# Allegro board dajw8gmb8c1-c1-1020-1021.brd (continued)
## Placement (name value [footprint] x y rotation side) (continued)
PC177  0.1U/25V_4  [CC0402]  171.77 26.01 90 bottom
PC178  2200P/50V_4  [CC0402]  154.32 25.67 180 bottom
PC179  *2200P/50V_4_NC  [CC0402]  119.91 25.04 180 bottom
PC180  0.1U/25V_4  [CC0402]  154.32 24.53 180 bottom
PC181  *2200P/50V_4_NC  [CC0402]  136.92 24.4 0 bottom
PC182  *2200P/50V_4_NC  [CC0402]  166.38 22.63 270 bottom
PC183  4.7U/25V_8  [CC0805]  152.38 20.69 270 bottom
PC184  4.7U/25V_8  [CC0805]  125.1 21.7 270 bottom
PC185  4.7U/25V_8  [CC0805]  123.07 21.7 270 bottom
PC186  0.1U/25V_4  [CC0402]  150.73 20.43 90 bottom
PC187  0.1U/25V_4  [CC0402]  129.32 21.32 270 bottom
PC188  0.1U/25V_4  [CC0402]  127.11 21.32 270 bottom
PC189  4.7U/25V_8  [CC0805]  134.87 19.74 270 bottom
PC190  4.7U/25V_8  [CC0805]  132.73 19.73 270 bottom
PC191  10U/25V_8  [CC0805]  32.23 17.48 0 bottom
PC192  4.7U/25V_8  [CC0805]  156.22 17.29 180 bottom
PC193  2200P/50V_4  [CC0402]  134.28 16.78 90 bottom
PC194  0.1U/25V_4  [CC0402]  135.35 16.77 90 bottom
PC195  2200P/50V_4  [CC0402]  124.16 16.95 90 bottom
PC196  0.1U/25V_4  [CC0402]  122.89 16.95 270 bottom
PC197  10U/25V_8  [CC0805]  32.24 15.44 0 bottom
PC198  0.1U/25V_4  [CC0402]  32.49 13.83 0 bottom
PC199  0.01U/25V_4  [CC0402]  30.84 13.32 90 bottom
PC200  0.1U/25V_4  [CC0402]  32.49 12.69 0 bottom
PC240  4.7U/6.3V_6  [CC0603]  63.2 19.57 90 top
PC241  0.022U/16V_4  [CC0402]  53.32 20.35 90 top
PC249  1U/6.3V/X5R  [CC0402]  243.19 43.17 270 top
PC250  0.1U/16V/X7R_4  [CC0402]  249.28 44.31 270 top
PC251  10U/6.3V/X5R_6  [CC0603]  250.43 44.56 270 top
PC252  0.1U/16V/X7R_4  [CC0402]  251.7 40.5 90 top
PC253  10U/6.3V/X5R_6  [CC0603]  250.93 42.66 180 top
PC254  1000P/50V_4  [CC0402]  233.24 48.2 270 top
PD1  *Dis@BAT54C T/R_NC  [UMT_213-3-1_3]  249.03 48.12 90 top
PD2  SDM10K45-7-F  [DSMV]  42.53 29.83 180 top
PD3  SDM10K45-7-F  [DSM]  178.07 29.61 180 top
PD4  *Dis@1N4448WS_NC  [DSM]  89.01 23.99 270 top
PD5  1SS355  [DSMV]  43.01 19.7 0 top
PD6  *1N4448WS_NC  [DSM]  212.5 118.31 0 bottom
PD7  *Dis@1N4448WS_NC  [DSM]  262.11 47.99 180 top
PD8  1SS355  [DSMV]  61.77 25.51 180 top
PL1  1UH (PCMC063T-1R0MN)  [CHOKE-MPL73-1R5]  189.14 122.95 180 bottom
PL2  2.2UH (TMPC0402HP-2R2MG-Z01)  [L4_06X4_06-1_8]  161.45 121.18 0 bottom
PL3  0.24UH (ETQP4LR24AFM)  [CHOKE-PCMC063T-R82MN-4P-SMT]  139.4 120.84 180 bottom
PL4  *0.24UH (ETQP4LR24AFM)_NC  [CHOKE-PCMC063T-R82MN-4P-SMT]  129.93 120.84 0 bottom
PL5  0.36UH/30A  [CHOKE-ETQP4L]  220.07 64.25 180 bottom
PL6  0.36UH/30A  [CHOKE-ETQP4L]  207.43 63.25 90 bottom
PL7  4.7UH (PCMC063T-4R7MN)  [CHOKE-MPLC0730L3R3]  38.03 24.85 270 bottom
PL8  0.82UH_(EM-82BM05V04)  [CHOKE-MPL73-1R5]  159.14 26.39 90 bottom
PL9  2.2UH_(EM-22AM05V04)  [CHOKE-MPL73-1R5]  113.04 19.96 180 bottom
PL10  2.2UH_(EM-22AM05V04)  [CHOKE-MPL73-1R5]  144.99 19.5 180 bottom
PQ1  FDMC7678  [POWER-FDMC7678-5P]  171.18 119.37 180 top
PQ2  *Dis@2N7002KW_SC70_NC  [UMT_213-3-1_3]  215.25 118.35 0 top
PQ3  Dis@QM3002V  [TSOP6-2_8-95]  221.47 117.72 90 top
PQ4  FDMC7678  [POWER-FDMC7678-5P]  175.98 117 270 top
PQ5  *DMN66D0LDW-7_NC  [SOT-363]  20.81 89.47 180 top
PQ6  *DMN66D0LDW-7_NC  [SOT-363]  20.73 84.46 90 top
PQ7  Dis@FDMC7678  [POWER-FDMC7678-5P]  226.8 71.61 90 top
PQ8  *Dis@2N7002KW_SC70_NC  [UMT_213-3-1_3]  245.35 49.26 270 top
PQ9  FDC8886  [SSOT6-2_8-95]  190.61 39.61 0 top
PQ10  FDC8886  [SSOT6-2_8-95]  190.61 35.29 180 top
PQ12  METR5213-G  [UMT_213-3-1_3]  123.46 31.9 270 top
PQ13  2N7002KW_SC70  [UMT_213-3-1_3]  126.25 31.77 90 top
PQ14  2N7002KW_SC70  [UMT_213-3-1_3]  140.85 31.77 0 top
PQ15  METR5213-G  [UMT_213-3-1_3]  144.66 31.77 0 top
PQ16  DMN66D0LDW-7  [SOT-363]  50.48 23.53 270 top
PQ17  MMDT2907A  [SOT363-2_1-65-6P]  35.72 25.49 270 top
PQ18  Dis@METR5213-G  [UMT_213-3-1_3]  91.55 23.74 270 top
PQ19  FDC8886  [SSOT6-2_8-95]  235.95 22.85 270 top
PQ20  FDMC4435BZ  [PG-TSDSON-8-8P-R]  38.55 20.55 90 top
PQ21  2N7002W  [UMT_213-3-1_3]  55.84 20.08 180 top
PQ22  2N7002W  [UMT_213-3-1_3]  32.72 14.13 270 top
PQ23  FDMC8884  [PG-TSDSON-8-8P-R]  195.77 124.78 180 bottom
PQ24  *CSD97374CQ4M_NC  [SON8-4_5X3_5-5-9P-SMT]  122.66 122.59 270 bottom
PQ25  Dis@2N7002KW_SC70  [UMT_213-3-1_3]  214.99 121.14 180 bottom
PQ26  CSD97374CQ4M  [SON8-4_5X3_5-5-9P-SMT]  146.87 119.52 90 bottom
PQ27  Dis@2N7002KW_SC70  [UMT_213-3-1_3]  217.41 118.35 180 bottom
PQ28  FDMS0310AS  [SO-8FL-5P]  196.2 118.22 0 bottom
PQ29  Dis@2N7002KW_SC70  [UMT_213-3-1_3]  222.99 116.7 0 bottom
PQ30  Dis@MDU1512RH  [SO-8FL-5P]  195.69 111.62 0 bottom
PQ31  *IMD2AT108_NC  [SC74-2_8-95-6P]  23.77 90.9 270 bottom
PQ32  AON7403  [PG-TSDSON-8-8P-R]  19.29 87.49 90 bottom
PQ33  *Dis@2N7002KW_SC70_NC  [UMT_213-3-1_3]  228.07 71.61 180 bottom
PQ34  *Dis@2N7002KW_SC70_NC  [UMT_213-3-1_3]  188.07 67.8 0 bottom
PQ35  FDMC4435BZ  [PG-TSDSON-8-8P-R]  30.97 60.31 270 bottom
PQ36  FDMS0308S  [SO-8FL-5P]  225.1 56.29 270 bottom
PQ37  *Dis@2N7002KW_SC70_NC  [UMT_213-3-1_3]  196.71 55.87 0 bottom
PQ38  FDMS7682  [SO-8FL-5P]  217.04 54.88 0 bottom
PQ39  FDMS0308S  [SO-8FL-5P]  204.43 54.3 270 bottom
PQ40  FDMS7682  [SO-8FL-5P]  210.98 52.35 90 bottom
PQ41  Dis@METR5213-G  [UMT_213-3-1_3]  255.76 48.37 0 top
PQ42  FDMC8884  [PG-TSDSON-8-8P-R]  35.67 31.86 90 bottom
PQ43  FDMC8884  [PG-TSDSON-8-8P-R]  39.61 31.86 270 bottom
PQ44  FDMC7692S  [PG-TSDSON-8-8P-R]  119.65 22.37 0 bottom
PQ45  FDMC7692S  [PG-TSDSON-8-8P-R]  138.36 21.86 180 bottom
PQ46  FDMC8884  [PG-TSDSON-8-8P-R]  155.87 20.34 0 bottom
PQ47  FDMS0310AS  [SO-8FL-5P]  161.05 19.2 0 bottom
PQ48  FDMC8884  [PG-TSDSON-8-8P-R]  119.62 18.3 180 bottom
PQ49  FDMC8884  [PG-TSDSON-8-8P-R]  138.31 17.67 0 bottom
PQ50  DMN66D0LDW-7  [SOT-363]  60.56 19.8 180 top
PQ901  BC856B  [SOT23_123-2_37-1_9-1_11H]  59.55 22.72 90 top
PR1  10_6  [RC0603]  207.3 122.97 270 top
PR2  *0_4/S  [SHORT0402]  116.19 121.27 180 top
PR3  *0_4_NC  [RC0402]  116.19 120.13 0 top
PR4  2.2K/F_4  [RC0402]  108.82 119.87 270 top
PR6  130_4  [RC0402]  115.17 118.99 0 top
PR7  *0_4/S  [SHORT0402]  208.39 118.96 0 top
PR8  *0_2/S  [SHORT0201]  184.41 118.88 0 top
PR9  Dis@22_8  [RC0805]  211.56 118.35 180 top
PR10  54.9/F_4  [RC0402]  115.17 117.97 0 top
PR11  1K_4  [RC0402]  115.93 116.83 180 top
PR12  100_4  [RC0402]  164.83 116.45 270 top
PR13  *0_4/S  [SHORT0402]  107.3 117.97 180 top
PR14  *0_4_SHORT_NC  [SHORT0402]  169.65 114.92 90 top
PR15  10K_4  [RC0402]  180.5 117.21 270 top
PR16  150K/F_4  [RC0402]  106.66 111.75 90 top
PR17  75K/F_4  [RC0402]  107.68 111.75 90 top
PR18  150K/F_4  [RC0402]  109.08 111.75 90 top
PR19  *562K/F_4_NC  [RC0402]  106.28 109.33 270 top
PR20  499K/F_4  [RC0402]  107.42 109.33 270 top
PR21  9.31K/F_4  [RC0402]  108.57 109.33 270 top
PR22  *2.4K_12_NC  [RC1206]  20.15 91.66 180 top
PR23  *1K_4_NC  [RC0402]  18.28 89.08 270 top
PR24  *10K_4_NC  [RC0402]  16.76 88.69 180 top
PR25  *0_4_NC  [RC0402]  22.29 85.5 90 top
PR26  *6.8K/F_4_NC  [RC0402]  22.29 83.35 270 top
PR27  *6.8K/F_4_NC  [RC0402]  23.43 83.34 270 top
PR28  *1K_4_NC  [RC0402]  21.13 81.29 0 top
PR29  *Dis@22_8_NC  [RC0805]  188.07 66.92 0 top
PR31  100R/J_4  [RC0402]  194.64 61.74 90 top
PR32  *0_4_NC  [RC0402]  112.76 60.82 90 top
PR33  100R/J_4  [RC0402]  195.67 60.2 180 top
PR34  2_6  [RC0603]  234.41 57.37 270 top
PR35  2.2R_8  [RC0805]  231 57.26 180 top
PR36  10K/F_4  [RC0402]  233.3 57.15 90 top
PR37  5.9K/F_4  [RC0402]  238.1 57.07 90 top
PR38  *short  [SHORT-1A]  240.14 56.76 180 top
PR39  *0_4/S  [SHORT0402]  111.36 56.25 90 top
PR40  82K/F_4  [RC0402]  239.77 55.24 0 top
PR41  *0_4_NC  [RC0402]  111.36 54.09 270 top
PR42  43K/F_4  [RC0402]  238.73 53.19 180 top
PR43  51_4  [RC0402]  241.01 53.19 180 top
PR44  10K/F_4  [RC0402]  240.99 52.18 180 top
PR45  21K/F_4  [RC0402]  228.35 51.76 0 top
PR46  18K/F_4  [RC0402]  239.26 50.65 270 top
PR47  20K/F_4  [RC0402]  241.3 50.64 90 top
PR48  2K/F_4  [RC0402]  240.29 50.63 90 top
PR49  Dis@0_4  [RC0402]  248.39 50.53 0 top
PR50  *Dis@0_4_SHORT_NC  [SHORT0402]  243.19 49.9 270 top
PR51  *0_4/S  [SHORT0402]  238.74 49.11 180 top
PR52  *0_4_NC  [RC0402]  234.77 48.63 0 top
PR53  2.2R_8  [RC0805]  230.86 48.12 180 top
PR54  DIS@100K_4  [RC0402]  232.73 46.48 180 top
PR55  *0_4/S  [SHORT0402]  236.35 48.12 270 top
PR56  20K/F_4  [RC0402]  237.94 48.1 0 top
PR57  *Dis@100K_4_NC  [RC0402]  242.96 46.8 270 top
PR58  10K/F_4  [RC0402]  234.77 47.61 180 top
PR59  *Dis@100K_4_NC  [RC0402]  245.47 46.72 180 top
PR60  *0_4/S  [SHORT0402]  234.78 46.59 180 top
PR61  *0_4_SHORT_NC  [SHORT0402]  279.26 39.48 0 top
PR62  10_6  [RC0603]  49.18 32.75 270 top
PR63  7.5_6  [RC0603]  50.4 32.75 90 top
PR64  22K/F_4  [RC0402]  51.8 30.47 0 top
PR65  100K/F_4  [RC0402]  52.18 32.63 0 top
PR66  *0_4/S  [SHORT0402]  169.65 33.77 0 top
PR67  316K/F_4  [RC0402]  53.42 30.02 90 top
PR68  2.2_8  [RC0805]  35.38 33.48 270 top
PR69  6.65K/F_4  [RC0402]  130.43 33.42 0 top
PR70  *SJ0402_NC  [SHORT0402]  51.57 29.35 0 top
PR71  1K_4  [RC0402]  191.63 32.88 180 top
PR72  0_6  [RC0603]  43.39 28.31 0 top
PR73  *0_6_SHORT_NC  [SHORT0603]  276.54 35.47 90 top
PR74  10K/F_4  [RC0402]  134.25 32.53 270 top
PR75  15.4K/F_4  [RC0402]  135.39 32.53 270 top
PR76  10K/F_4  [RC0402]  130.43 32.41 0 top
PR77  12K/F_4  [RC0402]  174.99 32.37 0 top
PR78  100K/F_4  [RC0402]  120.28 32.15 180 top
PR79  90.9K/F_4  [RC0402]  128.1 32.14 270 top
PR80  619K/F_4  [RC0402]  169.94 31.9 90 top
PR81  15K/F_4  [RC0402]  173.37 31.9 270 top
PR82  *0_4_NC  [RC0402]  171.05 31.86 270 top
PR83  *SJ0402_NC  [SHORT0402]  51.57 28.21 0 top
PR85  90.9K/F_4  [RC0402]  136.78 31.01 180 top
PR86  100K/F_4  [RC0402]  177.18 31.03 180 top
PR87  35.7K/F_4  [RC0402]  53.09 26.81 270 top
PR88  10_6  [RC0603]  168.16 30.21 180 top
PR89  *10K/F_4_NC  [RC0402]  136.78 29.87 0 top
PR90  *0_4/S  [SHORT0402]  141.49 29.1 90 top
PR91  100K/F_4  [RC0402]  142.63 29.1 90 top
PR92  2_6  [RC0603]  137.07 28.6 0 top
PR93  220K_4  [RC0402]  36.5 28.55 180 top
PR94  220K/F_4  [RC0402]  53.1 24.66 270 top
PR95  1M_4  [RC0402]  34.98 28.03 270 top
PR96  10K_4  [RC0402]  48.91 24.41 270 top
PR97  220K_4  [RC0402]  36.5 27.53 0 top
PR98  2_6  [RC0603]  124.75 27.33 0 top
PR99  7.5K/F_4  [RC0402]  168.41 26.94 180 top
PR100  Dis@1M_4  [RC0402]  93.45 24.75 90 top
PR101  Dis@1M_4  [RC0402]  94.47 24.75 270 top
PR102  12.4K/F_4  [RC0402]  52.04 22.86 270 top
PR103  10_12  [RC1206]  43.49 23.66 270 top
PR104  10K/F_4  [RC0402]  48.91 22.38 90 top
PR105  *Dis@0_4/S  [SHORT0402]  87.36 25.13 270 top
PR106  *665K/F_4_NC  [RC0402]  128.66 23.91 270 top
PR107  *330K/F_4_NC  [RC0402]  129.81 23.89 90 top
PR108  267K/F_4  [RC0402]  47.48 21.83 180 bottom
PR109  1M_4  [RC0402]  36.17 22.92 270 top
PR110  2M/F_4  [RC0402]  49.06 20.31 90 bottom
PR111  120K/F_4  [RC0402]  47.48 20.81 0 bottom
PR112  12.4K/F_4  [RC0402]  47.48 18.78 0 bottom
PR113  10_8  [RC0805]  131.46 21.61 90 top
PR114  1K_6  [RC0603]  35.06 21.48 90 top
PR115  10K/F_4  [RC0402]  47.48 19.8 180 bottom
PR116  1K_4  [RC0402]  233.79 19.47 270 top
PR117  22_6  [RC0603]  198.99 19.29 0 top
PR118  470_8  [RC0805]  32.42 17.08 0 top
PR119  2.87K/F_4  [RC0402]  135.7 126.1 0 bottom
PR120  2.2_8  [RC0805]  147.3 125.59 180 bottom
PR121  *2.87K/F_4_NC  [RC0402]  129.65 125.49 90 bottom
PR122  *1.74K/F_4_NC  [RC0402]  128.51 125.49 270 bottom
PR123  1.6K/F_4  [RC0402]  137.93 125.41 270 bottom
PR124  *0_4_NC  [RC0402]  209.02 125.08 270 bottom
PR125  *10K/NTC/TSM0B103J4252RE_4_NC  [RC0402]  132.16 125 0 bottom
PR126  10K/NTC/TSM0B103J4252RE_4  [RC0402]  135.87 125.08 0 bottom
PR127  76.8K/F_4  [RC0402]  169.2 124.8 90 bottom
PR128  2_6  [RC0603]  205.87 124.64 180 bottom
PR129  1K_4  [RC0402]  163.33 124.4 0 bottom
PR130  *0_4/S  [SHORT0402]  210.93 124.07 0 bottom
PR131  *0_6_NC  [RC0603]  118.6 123.38 0 bottom
PR132  10_6  [RC0603]  115.86 123.35 180 bottom
PR133  51.1K/F_4  [RC0402]  169.99 123.15 180 bottom
PR134  *0_4_NC  [RC0402]  211.93 122.88 0 bottom
PR135  *2.2_6_NC  [RC0603]  194.88 122.08 0 bottom
PR136  10K/F_4  [RC0402]  211.93 121.86 0 bottom
PR137  *0_4/S  [SHORT0402]  117.33 121.65 90 bottom
PR138  *0_4/S  [SHORT0402]  116.19 121.65 90 bottom
PR139  5.76K/F_4  [RC0402]  106.97 120.81 0 bottom
PR140  100K/F_4  [RC0402]  210.91 120.72 0 bottom
PR141  Dis@1M_4  [RC0402]  218.17 120.64 0 bottom
PR142  *0_4/S  [SHORT0402]  115.04 120.64 90 bottom
PR143  10K/F_4  [RC0402]  109.13 120.61 0 bottom
PR145  *0_4/S  [SHORT0402]  112.94 120.33 90 bottom
PR146  DIS@120K/F_4  [RC0402]  221.09 119.87 180 bottom
PR147  *0_4_NC  [RC0402]  210.91 119.7 0 bottom
PR148  *0_4_NC  [RC0402]  208.18 118.79 90 bottom
PR149  61.9K/F_4  [RC0402]  209.21 118.78 270 bottom
PR150  10K/F_4  [RC0402]  207.05 118.78 270 bottom
PR151  Dis@1M_4  [RC0402]  221.09 118.73 0 bottom
PR152  *0_4/S  [SHORT0402]  107.04 118.76 0 bottom
PR153  10_6  [RC0603]  115.83 118.3 180 bottom
PR154  *0_4/S  [SHORT0402]  105.34 118.3 270 bottom
PR155  0_6  [RC0603]  150.81 118.02 180 bottom
PR156  *0_4/S  [SHORT0402]  107.04 117.74 0 bottom
PR158  *2.2_8_NC  [RC0805]  124.03 116.67 0 bottom
PR159  *0_4_NC  [RC0402]  115.46 116.19 180 bottom
PR160  *16K/F_4_NC  [RC0402]  105.32 116.14 90 bottom
PR161  *0_4_NC  [RC0402]  115.48 115.05 180 bottom
PR162  *0_4_NC  [RC0402]  118.09 114.16 180 bottom
PR163  *0_4/S  [SHORT0402]  115.48 114.03 0 bottom
PR164  63.4K/F_4  [RC0402]  105.37 113.91 270 bottom
PR165  *0_4/S  [SHORT0402]  118.09 113.02 0 bottom
PR166  348K/F_4  [RC0402]  110.98 111.75 90 bottom
PR167  *10K/F_4_NC  [RC0402]  106.61 111.72 90 bottom
PR168  10K/F_4  [RC0402]  105.47 111.72 270 bottom
PR169  39K/F_4  [RC0402]  107.7 111.71 90 bottom
PR170  75K/F_4  [RC0402]  110.35 110.1 0 bottom
PR171  10K/F_4  [RC0402]  108.24 110.07 180 bottom
PR172  100K/NTC/B4250_4  [RC0402]  106.08 110.07 180 bottom
PR173  240K_4  [RC0402]  21.77 91.35 90 bottom
PR174  47K_4  [RC0402]  21.77 89.26 90 bottom
PR175  Dis@22_8  [RC0805]  231.05 72.5 90 bottom
PR177  NTC_100K_4  [RC0402]  213.11 59.27 270 bottom
PR178  *0_4/S  [SHORT0402]  233.41 58.79 0 bottom
PR179  Dis@22_8  [RC0805]  194.29 58.66 180 bottom
PR180  10K_4  [RC0402]  30.18 57.34 180 bottom
PR181  *10K/F_4_NC  [RC0402]  233.41 57.09 180 bottom
PR182  100K_4  [RC0402]  30.83 56.3 180 bottom
PR183  0.01_0612  [RC3216-4P]  35.18 56.04 180 bottom
PR184  2.2_6  [RC0603]  228.99 53.18 270 bottom
PR186  2.2_6  [RC0603]  200.54 52.56 270 bottom
PR188  Dis@1M_4  [RC0402]  253.5 47.74 270 top
PR189  *0_4/S  [SHORT0402]  237.62 47.23 0 bottom
PR190  Dis@47K/F_4  [RC0402]  258.17 48.12 90 top
PR191  Dis@1M_4  [RC0402]  253.5 49.77 270 top
PR192  *0_4/S  [SHORT0402]  237.62 46.22 0 bottom
PR193  *SJ0402_NC  [SHORT0402]  45.45 20.81 0 bottom
PR194  *0_2/S  [SHORT0201]  115.95 29.37 0 bottom
PR195  *0_2/S  [SHORT0201]  166.63 29.12 90 bottom
PR196  *0_2/S  [SHORT0201]  145.55 26.82 180 bottom
PR197  2_6  [RC0603]  173.01 26.28 90 bottom
PR198  *2.2_6_NC  [RC0603]  117.49 25.04 0 bottom
PR199  *2.2_6_NC  [RC0603]  139.33 24.4 180 bottom
PR200  *2.2_6_NC  [RC0603]  164.22 23.06 0 bottom
PR201  0.01_0612  [RC3216-4P]  35.82 18.43 180 bottom
PR202  330_4  [RC0402]  25.51 13.07 270 bottom
PR203  330_4  [RC0402]  27.35 11.73 180 bottom
PR204  200K/J_4  [RC0402]  29.52 11.72 0 bottom
PR205  1K/F_4  [RC0402]  31.73 11.67 180 bottom
PR206  *0_4_NC  [RC0402]  106.36 116.32 90 top
PR207  1K_4  [RC0402]  194.7 40.17 90 top
PR424  100K_4  [RC0402]  57.13 24.12 90 top
PR425  680K/F_4  [RC0402]  58.15 19.8 90 top
PR426  10K/F_4  [RC0402]  63.2 22.08 90 top
PR427  100K_4  [RC0402]  63.59 17.77 180 top
PR428  150K_4  [RC0402]  52.31 20.35 270 top
PR432  3.83K/F  [RC0402]  250.68 40.5 90 top
PR434  10K/F_4  [RC0402]  249.66 40.5 90 top
PU1  NCP81172MNTXG  [QFN24-4X4-5-25P]  234.15 52.64 0 top
PU2  TPS22965DSGR  [SON8-2X2-5-9P]  282.18 39.74 270 top
PU3  BQ24737RGRR  [PVQFN20-3_5X3_5-5-25P]  47.73 28.29 0 top
PU4  RT8223PZQW  [QFN24-4X4-5-25P]  131.46 28.09 180 top
PU5  RT8207LGQW  [QFN24-4X4-5-25P]  172.83 27.66 90 top
PU6  SLG55448VTR  [TQFN20-3X3-4-21P]  202.93 21.83 90 top
PU7  RT8068AZQW  [DFN10-3X3-5-11P-RT9296]  166.59 122.26 90 bottom
PU8  RT8240BZQW  [WQFN12-2X2-4-13P-SMT]  207.75 121.96 0 bottom
PU9  TPS51622RSM  [QFN32-4X4-4-42P-1H]  111.1 116.16 180 bottom
PU11  G9183-12TP1U  [SOT23-6-4_2-95-6P]  246.24 42.79 180 top
Q1  2N7002W  [UMT_213-3-1_3]  158.61 125.21 0 top
Q3  DMN66D0LDW-7  [SOT-363]  166.61 116.57 270 top
Q4  AP2319GN-HF  [SOT23_213-3_3-2]  155.68 114.54 270 top
Q5  PMF780SN  [UMT_213-3-1_3]  160.51 114.41 270 top
Q6  2N7002W  [UMT_213-3-1_3]  122.66 113.91 180 top
Q7  MMST3904-7-F  [UMT_213-3-1_3]  139.81 91.57 0 top
Q8  Dis@DTC144EUA  [UMT_213-3-1_3]  180.45 76.19 90 top
Q9  Dis@DTC144EUA  [UMT_213-3-1_3]  180.45 72.5 90 top
Q13  2N7002W  [UMT_213-3-1_3]  117.92 69.46 0 top
Q14  Dis@DMN66D0LDW-7  [SOT-363]  186.42 69.2 180 top
Q15  Dis@DMN66D0LDW-7  [SOT-363]  176 64.12 90 top
Q16  Dis@2N7002W  [UMT_213-3-1_3]  188.2 63.49 270 top
Q17  DMN66D0LDW-7  [SOT-363]  117.97 63.23 180 top
Q18  PMF780SN  [UMT_213-3-1_3]  110.22 47.36 270 top
Q19  *DMN66D0LDW-7_NC  [SOT-363]  107.3 45.71 270 top
Q20  *DMN66D0LDW-7_NC  [SOT-363]  259.57 44.56 0 top
Q21  2N7002W  [UMT_213-3-1_3]  67.9 37.12 90 top
Q23  2N7002W  [UMT_213-3-1_3]  68.44 32.75 0 top
Q24  DMN66D0LDW-7  [SOT-363]  285.3 32.75 180 top
Q25  ME2306  [SOT23_213-3_3-2]  290.05 31.48 0 top
Q26  2N7002W  [UMT_213-3-1_3]  279.64 27.67 180 top
Q27  *2N7002W_NC  [UMT_213-3-1_3]  92.06 27.16 0 top
Q28  AO3409  [SOT23_213-3_3-2]  283.07 29.45 270 bottom
Q29  *FDC8886_NC  [SSOT6-2_8-95]  83.8 28.94 0 top
Q30  *2N7002W_NC  [UMT_213-3-1_3]  57.39 27.42 90 top
Q31  ME2306  [SOT23_213-3_3-2]  287.18 25.26 270 top
Q32  DMN66D0LDW-7  [SOT-363]  187.31 19.8 270 top
Q33  2N7002W  [UMT_213-3-1_3]  189.97 19.8 270 top
Q34  DMN66D0LDW-7  [SOT-363]  174.35 86.22 270 bottom
Q35  Dis@MMST3904-7-F  [UMT_213-3-1_3]  181.72 77.28 0 bottom
Q36  Dis@DTC144EUA  [UMT_213-3-1_3]  178.29 76.69 270 bottom
Q37  DMN66D0LDW-7  [SOT-363]  171.18 74.03 270 bottom
Q38  Dis@MMST3904-7-F  [UMT_213-3-1_3]  181.72 73.77 0 bottom
Q39  *Dis@2N7002W_NC  [UMT_213-3-1_3]  187.05 72.88 90 bottom
Q40  *DMN66D0LDW-7_NC  [SOT-363]  304.78 72.38 90 bottom
Q41  2N7002W  [UMT_213-3-1_3]  269.17 45.58 0 bottom
Q42  2N7002W  [UMT_213-3-1_3]  284.21 39.99 0 bottom
Q43  2N7002W  [UMT_213-3-1_3]  240.39 35.04 180 bottom
Q44  DMN66D0LDW-7  [SC70-2_1-65-6P]  104.2 45.73 270 top
Q45  2N7002KDW  [SOT-363]  92.57 31.36 270 top
Q46  2N7002KDW  [SOT-363]  90.15 31.36 270 top
Q47  2N7002W  [UMT_213-3-1_3]  169.91 70.47 0 top
Q48  BSS138W  [UMT_213-3-1_3]  313.28 28.4 90 bottom
R1  150_6  [RC0603]  155.3 125.03 180 top
R2  150_6  [RC0603]  170.42 125.97 180 top
R3  150_6  [RC0603]  180.02 126.05 180 top
R4  330_4  [RC0402]  158.99 117.46 90 top
R5  330_4  [RC0402]  161.27 117.46 270 top
R6  *10K_4_NC  [RC0402]  170.8 114.92 270 top
R7  100K_4  [RC0402]  171.94 114.92 90 top
R8  *Dis@10K/F_4_NC  [RC0402]  173.08 114.92 90 top
R9  *10K_4_NC  [RC0402]  118.85 114.16 90 top
R10  51_4  [RC0402]  120.12 114.16 270 top
R11  10K_4  [RC0402]  158.12 113.6 90 top
R12  1K_4  [RC0402]  122.03 110.98 270 top
R13  10K_4  [RC0402]  123.05 111.24 90 top
R14  10K_4  [RC0402]  124.19 111.24 90 top
R15  *10K_4_NC  [RC0402]  125.46 111.24 90 top
R16  1K_4  [RC0402]  157.97 110.73 180 top
R17  100K_4  [RC0402]  157.97 109.71 180 top
R18  10K_4  [RC0402]  125.46 108.32 90 top
R19  *0_4_SHORT_NC  [SHORT0402]  144.25 108.19 270 top
R20  3K/F_4  [RC0402]  145.4 108.19 90 top
R21  3K/F_4  [RC0402]  146.54 108.19 270 top
R22  24.9/F_4  [RC0402]  148.19 107.68 0 top
R23  Dis@162/F_4  [RC0402]  224.77 105.52 270 top
R24  *1K_4_NC  [RC0402]  172.58 104 0 top
R25  *1K_4_NC  [RC0402]  174.73 104 180 top
R26  *short0603_NC  [SHORT0603]  20.05 103.49 180 top
R27  Dis@10K/F_4  [RC0402]  224.77 103.49 90 top
R28  *10K_4_NC  [RC0402]  174.73 102.86 180 top
R29  *short0603_NC  [SHORT0603]  20.05 102.35 180 top
R30  Dis@100/F_4  [RC0402]  179.94 101.59 90 top
R31  Dis@243/F_4  [RC0402]  224.77 101.33 270 top
R32  10K_4  [RC0402]  174.48 101.21 180 top
R33  51_4  [RC0402]  113.27 100.7 315 top
R34  *10K_4_NC  [RC0402]  174.48 100.19 180 top
R35  Dis@10K/F_4  [RC0402]  180.45 99.94 0 top
R36  10K_4  [RC0402]  172.32 98.92 180 top
R37  150_6  [RC0603]  114.79 98.67 315 top
R38  10K_4  [RC0402]  174.48 98.54 180 top
R39  10K_4  [RC0402]  172.32 97.9 180 top
R40  10K_4  [RC0402]  166.23 97.52 180 top
R41  Dis@1.33K/F_4  [RC0402]  224.77 97.14 270 top
R42  10K_4  [RC0402]  172.32 96.89 180 top
R43  8.2K/J_4  [RC0402]  166.23 96.38 180 top
R44  *120/F_4_NC  [RC0402]  312.53 96 90 top
R45  10K_4  [RC0402]  172.32 95.87 180 top
R46  10K_4  [RC0402]  166.23 95.36 180 top
R47  Dis@1.33K/F_4  [RC0402]  224.77 95.11 90 top
R48  10K_4  [RC0402]  172.32 94.73 180 top
R49  Dis@100K/F_4  [RC0402]  179.68 94.6 90 top
R50  *Dis@0_4_SHORT_NC  [SHORT0402]  180.89 94.6 270 top
R51  10K_4  [RC0402]  166.23 94.35 180 top
R52  *120/F_4_NC  [RC0402]  313.55 94.22 90 top
R53  10K_4  [RC0402]  166.23 93.33 180 top
R54  *0_8_SHORT_NC  [SHORT0805]  146.79 93.2 90 top
R55  *120/F_4_NC  [RC0402]  312.53 92.7 90 top
R56  *0_4_SHORT_NC  [SHORT0402]  166.23 92.2 180 top
R57  *1K_4_NC  [RC0402]  112.89 91.3 0 top
R58  *1K_4_NC  [RC0402]  115.04 91.3 0 top
R59  *120/F_4_NC  [RC0402]  313.67 90.79 90 top
R60  *47K_4_NC  [RC0402]  172.58 89.72 180 top
R61  1K_4  [RC0402]  113.39 89.27 0 top
R62  *0_4_SHORT_NC  [SHORT0402]  173.34 88.51 180 top
R63  51_4  [RC0402]  111.23 88 180 top
R64  *Dis@60.4/F_4_NC  [RC0402]  206.61 87.87 0 top
R65  10K_4  [RC0402]  173.34 87.49 180 top
R66  10K_4  [RC0402]  175.37 87.24 0 top
R67  51_4  [RC0402]  111.23 86.85 180 top
R68  *Dis@60.4/F_4_NC  [RC0402]  206.61 86.73 0 top
R69  10K_4  [RC0402]  173.34 86.47 180 top
R70  Dis@40.2K/F_4  [RC0402]  178.8 86.47 180 top
R71  *Dis@0_4_SHORT_NC  [SHORT0402]  180.7 86.22 90 top
R72  4.99K/F_4  [RC0402]  315.07 86.09 0 top
R73  Dis@42.2/F_4  [RC0402]  206.61 85.58 180 top
R74  10K_4  [RC0402]  173.34 85.46 180 top
R75  *0_4_SHORT_NC  [SHORT0402]  305.67 85.33 270 top
R76  *4.7K_4_NC  [RC0402]  315.07 85.08 180 top
R77  10K_4  [RC0402]  173.34 84.44 180 top
R78  *10K_4_NC  [RC0402]  175.5 84.44 0 top
R79  *4.7K_4_NC  [RC0402]  315.07 84.06 0 top
R80  Dis@40.2/F_4  [RC0402]  206.61 83.81 0 top
R81  10K_4  [RC0402]  173.36 83.43 180 top
R82  *0_4_NC  [RC0402]  305.67 83.3 270 top
R83  *4.7K_4_NC  [RC0402]  315.07 83.04 180 top
R84  10K_4  [RC0402]  173.36 82.41 180 top
R85  Dis@243/F_4  [RC0402]  210.29 82.41 90 top
R86  Dis@10K/F_4  [RC0402]  226.04 82.41 0 top
R87  4.7K_4  [RC0402]  315.07 82.03 0 top
R88  10K_4  [RC0402]  173.34 81.39 180 top
R89  Dis@1.33K/F_4  [RC0402]  226.04 81.27 180 top
R91  *4.7K_4_NC  [RC0402]  315.07 81.01 0 top
R93  Dis@1.33K/F_4  [RC0402]  226.04 80.25 0 top
R94  Dis@10K/F_4  [RC0402]  178.67 80.12 180 top
R95  *0_4_SHORT_NC  [SHORT0402]  315.07 80 0 top
R96  Dis@2.2K_4  [RC0402]  185.91 79.62 90 top
R97  Dis@2.2K_4  [RC0402]  187.05 79.62 90 top
R98  Dis@10K/F_4  [RC0402]  188.2 79.62 90 top
R99  Dis@10K/F_4  [RC0402]  189.34 79.62 90 top
R100  *Dis@4.99K/F_4_NC  [RC0402]  191.27 80.12 0 top
R101  Dis@4.99K/F_4  [RC0402]  193.4 79.64 270 top
R102  10K_4  [RC0402]  173.34 78.73 180 top
R103  *0_4_SHORT_NC  [SHORT0402]  173.34 77.71 180 top
R104  Dis@4.7K_4  [RC0402]  178.04 77.33 0 top
R105  22.6/F_4  [RC0402]  150.6 76.82 270 top
R106  *1K_4_NC  [RC0402]  152.36 76.82 90 top
R107  49.9/F_4  [RC0402]  154.41 76.82 90 top
R108  49.9/F_4  [RC0402]  155.56 76.82 90 top
R109  *0_4_SHORT_NC  [SHORT0402]  173.34 76.69 0 top
R110  100/F_4  [RC0402]  121.9 76.58 270 top
R111  120/F_4  [RC0402]  123.05 76.58 270 top
R112  200/F_4  [RC0402]  124.57 76.57 270 top
R113  *Dis@0_4_NC  [RC0402]  178.04 76.31 180 top
R114  100K_4  [RC0402]  175.1 75.5 180 bottom
R115  2K/F_4  [RC0402]  111.74 73.65 90 top
R116  22_4  [RC0402]  148.45 72.88 90 top
R117  22_4  [RC0402]  149.59 72.88 90 top
R119  20K/F_4  [RC0402]  154.41 72.38 90 top
R120  1M_4  [RC0402]  155.56 72.38 270 top
R121  *10K_4_NC  [RC0402]  158.73 72.38 90 top
R122  10K_4  [RC0402]  159.75 72.38 90 top
R123  10K_4  [RC0402]  160.76 72.38 90 top
R124  10K_4  [RC0402]  161.78 72.38 90 top
R125  10K_4  [RC0402]  162.8 72.38 90 top
R126  Dis@4.7K_4  [RC0402]  185.91 71.61 270 top
R127  Dis@4.7K_4  [RC0402]  187.05 71.61 270 top
R128  *0_4_SHORT_NC  [SHORT0402]  111.62 71.11 180 top
R131  10K_4  [RC0402]  162.42 70.73 0 top
R132  *0_4_NC  [RC0402]  111.62 69.96 0 top
R134  *_0_4_SHORT_NC  [SHORT0402]  165.84 71.23 0 top
R135  *0_4_SHORT_NC  [SHORT0402]  175.47 74.69 270 top
R137  *0_4_SHORT_NC  [SHORT0402]  183.75 67.3 90 top
R138  47K_4  [RC0402]  118.85 66.41 270 top
R139  18.7K/F_4  [RC0402]  113.39 65.65 180 top
R140  470_4  [RC0402]  154.62 58.51 0 top
R141  *0_4_NC  [RC0402]  112.63 58.41 90 top
R142  *0_4_NC  [RC0402]  113.77 58.41 90 top
R143  *0_4_SHORT_NC  [SHORT0402]  114.92 58.41 270 top
R145  75_4  [RC0402]  312.53 55.99 180 top
R146  *0_4_NC  [RC0402]  115.43 55.87 90 top
R147  75_4  [RC0402]  312.53 54.72 180 top
R148  *0_4_SHORT_NC  [SHORT0402]  115.43 53.58 90 top
R149  *0_6_SHORT_NC  [SHORT0603]  245.98 52.82 270 top
R150  2M_4  [RC0402]  108.06 51.68 270 top
R151  220K/F_4  [RC0402]  109.2 51.68 270 top
R152  *0_4_SHORT_NC  [SHORT0402]  112.89 50.28 90 top
R153  24.9/F_4  [RC0402]  113.9 50.28 90 top
R154  *0_4_SHORT_NC  [SHORT0402]  110.22 49.9 180 top
R155  100K_4  [RC0402]  107.68 48.5 180 top
R156  75_4  [RC0402]  312.53 48.37 180 top
R157  *0_4_SHORT_NC  [SHORT0402]  186.04 47.99 180 top
R158  2.2/F_4  [RC0402]  113.39 47.74 180 top
R159  75_4  [RC0402]  312.53 47.1 180 top
R160  *0_4_SHORT_NC  [SHORT0402]  186.04 46.85 180 top
R161  1.8K/F_4  [RC0402]  113.39 45.71 180 top
R162  *0_4_SHORT_NC  [SHORT0402]  186.04 45.71 180 top
R164  10K/F_4  [RC0402]  176.77 44.82 90 top
R165  10K/F_4  [RC0402]  178.04 44.82 270 top
R166  1.8K/F_4  [RC0402]  115.68 44.56 270 top
R167  66.5/F_4  [RC0402]  109.84 44.31 270 top
R168  66.5/F_4  [RC0402]  110.85 44.31 270 top
R169  *0_4_SHORT_NC  [SHORT0402]  260.08 42.4 270 top
R171  *10K_4_NC  [RC0402]  263.13 42.02 180 top
R172  *0_4_SHORT_NC  [SHORT0402]  258.94 42.4 270 top
R173  *10K_4_NC  [RC0402]  263.13 43.17 180 top
R174  *0_6_SHORT_NC  [SHORT0603]  283.7 41.64 0 top
R175  100K_4  [RC0402]  213.44 36.38 90 top
R176  *0_NC  [RC0402]  205.72 41.13 180 top
R177  *0_4_SHORT_NC  [SHORT0402]  53.07 40.65 180 top
R179  *0_4_SHORT_NC  [SHORT0402]  205.72 39.99 0 top
R181  *0_4_SHORT_NC  [SHORT0402]  217.28 38.72 0 top
R182  *0_4_NC  [RC0402]  215.12 39.86 0 top
R183  *0_4_SHORT_NC  [SHORT0402]  215.12 38.72 180 top
R186  15_4  [RC0402]  205.72 38.72 0 top
R188  10K_4  [RC0402]  53.07 38.34 180 top
R189  *0_4_SHORT_NC  [SHORT0402]  183.24 38.34 180 top
R192  *0_4_SHORT_NC  [SHORT0402]  205.72 37.71 0 top
R194  *0_4_SHORT_NC  [SHORT0402]  297.67 37.45 180 top
R195  0_4  [RC0402]  299.82 37.46 180 top
R196  *0_4_SHORT_NC  [SHORT0402]  183.24 37.32 180 top
R197  10K_4  [RC0402]  65.9 37.17 90 top
R198  *0_4_SHORT_NC  [SHORT0402]  163.43 37.07 0 top
R199  10K_4  [RC0402]  53.07 36.56 180 top
R200  1.8K/F_4  [RC0402]  154.54 36.56 90 top
R201  1.8K/F_4  [RC0402]  158.86 36.56 90 top
R202  2.2/F_4  [RC0402]  160.89 36.56 90 top
R203  *10K/F_4_NC  [RC0402]  177.15 36.56 90 top
R204  15_4  [RC0402]  205.72 36.56 180 top
R205  10K_4  [RC0402]  183.24 36.31 180 top
R207  24.9/F_4  [RC0402]  163.43 36.05 0 top
R210  75_4  [RC0402]  312.66 35.93 0 top
R211  0_4  [RC0402]  270.75 46.32 180 top
R214  0_4  [RC0402]  299.82 35.43 180 top
R215  *0_4_SHORT_NC  [SHORT0402]  295.44 35.27 180 top
R216  *0_4_SHORT_NC  [SHORT0402]  223.38 33.26 270 top
R217  75_4  [RC0402]  312.66 34.91 0 top
R218  *0_4_NC  [RC0402]  67.8 34.66 0 top
R219  6.2K/F_4  [RC0402]  62.21 34.15 0 top
R220  100K/F_4  [RC0402]  289.29 34.02 0 top
R221  10K_4  [RC0402]  236.58 33.9 0 top
R223  *0_4_NC  [RC0402]  216.64 33.77 0 top
R224  *0_6_SHORT_NC  [SHORT0603]  210.55 33.64 0 top
R225  10K_4  [RC0402]  79.46 34.05 90 top
R227  1K/F_4  [RC0402]  314.82 33.39 270 top
R229  *0_4_SHORT_NC  [SHORT0402]  54.59 33.13 270 top
R230  *0_4_SHORT_NC  [SHORT0402]  55.86 33.13 270 top
R231  1K_4  [RC0402]  297.15 33.15 180 top
R232  22_4  [RC0402]  299.83 33.01 180 top
R233  0_4  [RC0402]  76.82 39.74 0 top
R235  *0_4_NC  [RC0402]  265.51 34.56 90 top
R236  10K_4  [RC0402]  65.01 32.75 0 top
R238  10K_4  [RC0402]  264.5 34.56 90 top
R239  100K_4  [RC0402]  282.43 28.56 270 top
R240  0_12  [RC1206]  84.31 32.12 0 top
R243  *4.7K_4_NC  [RC0402]  55.74 30.59 90 top
R244  *100K_4_NC  [RC0402]  88.27 29.45 270 top
R245  43_4  [RC0402]  227.69 30.57 180 top
R246  390K_4  [RC0402]  281.82 32.04 90 top
R248  *0_4_SHORT_NC  [SHORT0402]  184.89 29.45 270 top
R249  *0_4_SHORT_NC  [SHORT0402]  185.91 29.45 270 top
R250  *0_6_SHORT_NC  [SHORT0603]  295.77 29.45 90 top
R253  *0_8_SHORT_NC  [SHORT0805]  284.21 28.94 90 top
R254  *10K_NC  [RC0402]  234.17 28.94 270 top
R255  *100K_4_NC  [RC0402]  235.19 28.94 90 top
R258  1K_4  [RC0402]  299.83 28.94 0 top
R259  4.7K_4  [RC0402]  195.44 28.69 270 top
R260  100K/F_4  [RC0402]  294.62 28.56 270 top
R261  39.2K/F_4  [RC0402]  303.13 28.43 270 top
R262  33_4  [RC0402]  304.4 28.43 270 top
R263  0_4  [RC0402]  305.42 28.43 270 top
R264  0_4  [RC0402]  306.48 28.43 270 top
R266  20K/F_4  [RC0402]  309.1 28.18 90 top
R267  2.2K_4  [RC0402]  310.12 28.18 270 top
R268  22K_4  [RC0402]  313.8 28.05 270 top
R269  4.7K_4  [RC0402]  195.44 26.66 90 top
R270  22K/F_4  [RC0402]  309.74 26.66 180 top
R272  100K/F_4  [RC0402]  294.62 26.4 270 top
R273  *0_6_NC  [RC0603]  297.04 25.89 180 top
R274  33_4  [RC0402]  207.63 25.26 90 top
R275  *0_4_SHORT_NC  [SHORT0402]  283.95 24.75 270 top
R276  *_0_8_SHORT_NC  [SHORT0805]  307.7 24.88 90 top
R277  100K/F_4  [RC0402]  291.8 24.67 180 top
R279  10K_4  [RC0402]  193.91 22.47 180 top
R280  100K_4  [RC0402]  185.4 20.81 90 top
R281  *0_8_SHORT_NC  [SHORT0805]  62.57 28.08 0 top
R282  100K_4  [RC0402]  185.4 18.66 270 top
R283  *0_12_NC  [RC1206]  164.45 117.21 180 bottom
R284  Dis@10K/F_4  [RC0402]  190.99 108.57 270 bottom
R285  Dis@2.49K/F_4  [RC0402]  202.24 108.47 90 bottom
R286  *Dis@200/F_4_NC  [RC0402]  194.85 107.91 180 bottom
R287  1M_4  [RC0402]  162.16 108.06 180 bottom
R288  *0_4_SHORT_NC  [SHORT0402]  157.72 106.03 0 bottom
R289  8.2K_4  [RC0402]  156.14 105.53 270 bottom
R290  *0_4_NC  [RC0402]  134.81 105.53 270 bottom
R291  *0_4_NC  [RC0402]  133.79 105.53 270 bottom
R292  1M_4  [RC0402]  141.67 105.15 0 bottom
R293  *0_4_SHORT_NC  [SHORT0402]  161.91 105.65 270 bottom
R294  3K/F_4  [RC0402]  157.72 105.02 180 bottom
R295  Dis@10K/F_4  [RC0402]  177.53 104.63 0 bottom
R296  Dis@1.33K/F_4  [RC0402]  224.77 103.87 270 bottom
R297  10K_4  [RC0402]  168.51 103.75 180 bottom
R298  10K_4  [RC0402]  163.94 102.62 180 bottom
R299  *1K_4_NC  [RC0402]  168.51 102.6 180 bottom
R300  *1K_4_NC  [RC0402]  166.23 102.6 0 bottom
R301  Dis@1.33K/F_4  [RC0402]  224.77 101.84 90 bottom
R302  Dis@243/F_4  [RC0402]  210.29 100.7 270 bottom
R303  Dis@10K/F_4  [RC0402]  224.77 99.68 90 bottom
R304  100/F_4  [RC0402]  117.71 99.48 0 bottom
R305  10K_4  [RC0402]  166.1 98.55 180 bottom
R306  100/F_4  [RC0402]  117.71 98.41 0 bottom
R307  *10K_4_NC  [RC0402]  164.07 97.78 180 bottom
R308  10K_4  [RC0402]  166.1 97.41 180 bottom
R309  56_4  [RC0402]  115.04 97.14 0 bottom
R310  10K_4  [RC0402]  163.94 96.63 180 bottom
R311  62_4  [RC0402]  113.39 96.25 270 bottom
R312  43_4  [RC0402]  117.71 96 0 bottom
R313  75_4  [RC0402]  115.04 96 180 bottom
R314  10K_4  [RC0402]  166.86 95.36 0 bottom
R315  *0_6_SHORT_NC  [SHORT0603]  164.45 95.36 0 bottom
R316  *130_4_NC  [RC0402]  117.71 94.86 180 bottom
R317  *62_4_NC  [RC0402]  115.04 94.86 0 bottom
R318  10K  [RC0402]  166.1 93.97 180 bottom
R319  10K_4  [RC0402]  163.94 93.97 180 bottom
R320  130_4  [RC0402]  117.71 93.71 180 bottom
R321  *75_4_NC  [RC0402]  115.04 93.71 180 bottom
R322  10K_4  [RC0402]  166.35 91.68 0 bottom
R323  10K_4  [RC0402]  164.19 91.68 180 bottom
R324  *0_4_SHORT_NC  [SHORT0402]  170.92 91.43 180 bottom
R325  49.9/F_4  [RC0402]  117.66 91.18 180 bottom
R326  *1K_4_NC  [RC0402]  115.5 91.18 0 bottom
R327  *47K_4_NC  [RC0402]  168.64 90.79 0 bottom
R328  10K_4  [RC0402]  166.35 90.54 0 bottom
R329  *0_4_NC  [RC0402]  170.92 90.41 0 bottom
R330  *1K_4_NC  [RC0402]  116.77 90.03 0 bottom
R331  10K_4  [RC0402]  166.35 89.52 180 bottom
R332  10K_4  [RC0402]  164.32 89.39 180 bottom
R333  *0_4_NC  [RC0402]  170.92 89.27 0 bottom
R334  *1K_4_NC  [RC0402]  117.66 88.89 0 bottom
R335  Dis@10K/F_4  [RC0402]  178.8 88.76 0 bottom
R336  10K_4  [RC0402]  164.32 88.38 180 bottom
R337  10K_4  [RC0402]  170.92 88.25 180 bottom
R338  10K_4  [RC0402]  166.35 88.12 0 bottom
R339  *1K_4_NC  [RC0402]  115.43 88 0 bottom
R340  51_4  [RC0402]  117.66 87.87 180 bottom
R341  Dis@10K/F_4  [RC0402]  210.29 87.74 90 bottom
R342  *Dis@15K/F_4_NC  [RC0402]  178.8 87.62 0 bottom
R343  *Dis@10K/F_4_NC  [RC0402]  176.64 87.62 0 bottom
R344  10K_4  [RC0402]  169.27 87.11 180 bottom
R345  10K_4  [RC0402]  166.35 86.98 0 bottom
R346  *1K_4_NC  [RC0402]  117.66 86.86 0 bottom
R347  0_4  [RC0402]  115.43 86.85 180 bottom
R348  *Dis@4.99K/F_4_NC  [RC0402]  178.8 86.47 0 bottom
R349  *Dis@10K/F_4_NC  [RC0402]  176.64 86.47 0 bottom
R350  10K_4  [RC0402]  169.27 85.97 180 bottom
R351  *51_4_NC  [RC0402]  117.66 85.84 180 bottom
R352  10K_4  [RC0402]  166.35 85.84 0 bottom
R353  *51_4_NC  [RC0402]  115.43 85.84 0 bottom
R354  10K_4  [RC0402]  164.19 85.58 180 bottom
R355  *Dis@10K/F_4_NC  [RC0402]  178.8 85.33 0 bottom
R356  Dis@49.9K/F_4  [RC0402]  176.64 85.33 0 bottom
R357  *4.7K_4_NC  [RC0402]  310.12 85.2 180 bottom
R358  10K_4  [RC0402]  169.27 84.82 180 bottom
R359  Dis@51.1/F_4  [RC0402]  208.01 84.7 0 bottom
R360  Dis@1.33K/F_4  [RC0402]  226.04 84.57 0 bottom
R361  *Dis@45.3K/F_4_NC  [RC0402]  178.8 84.31 0 bottom
R362  *Dis@10K/F_4_NC  [RC0402]  176.64 84.31 0 bottom
R363  *0_4_SHORT_NC  [SHORT0402]  312.5 83.17 180 bottom
R364  *Dis@45.3K/F_4_NC  [RC0402]  178.8 83.17 180 bottom
R365  10K_4  [RC0402]  173.34 83.04 180 bottom
R366  Dis@1.33K/F_4  [RC0402]  226.55 82.92 270 bottom
R367  4.7K_4  [RC0402]  312.5 82.16 0 bottom
R368  Dis@243/F_4  [RC0402]  226.55 80.76 270 bottom
R369  Dis@10K/F_4  [RC0402]  225.53 80.76 270 bottom
R370  *4.7K_4_NC  [RC0402]  314.18 80.5 270 bottom
R371  *Dis@4.7K_4_NC  [RC0402]  178.67 80.12 180 bottom
R372  Dis@10K/F_4  [RC0402]  182.74 79.74 180 bottom
R373  Dis@2.2K_4  [RC0402]  187.82 79.36 270 bottom
R374  Dis@2.2K_4  [RC0402]  186.8 79.36 270 bottom
R375  Dis@2.2K_4  [RC0402]  185.78 79.36 90 bottom
R376  Dis@2.2K_4  [RC0402]  184.77 79.36 90 bottom
R377  Dis@100K/F_4  [RC0402]  178.67 79.11 0 bottom
R378  Dis@162/F_4  [RC0402]  225.53 78.73 90 bottom
R379  *0_4_SHORT_NC  [SHORT0402]  299.7 29.96 0 top
R380  *4.7K_4_NC  [RC0402]  306.05 78.35 90 bottom
R381  Dis@10K/F_4  [RC0402]  187.94 76.95 90 bottom
R382  Dis@10K/F_4  [RC0402]  186.88 76.95 90 bottom
R383  *4.7K_4_NC  [RC0402]  307.22 77.57 90 bottom
R384  *100K_4_NC  [RC0402]  305.67 76.19 270 bottom
R385  10M_4  [RC0402]  164.32 75.93 0 bottom
R386  Dis@4.7K_4  [RC0402]  184.89 75.37 180 bottom
R387  *0_4_SHORT_NC  [SHORT0402]  169.15 75.81 90 bottom
R388  *100K_4_NC  [RC0402]  168.13 75.81 90 bottom
R389  *100K_4_NC  [RC0402]  162.75 75.35 270 bottom
R390  *_0_4_SHORT_NC  [SHORT0402]  161.6 75.32 270 bottom
R391  *0_4_SHORT_NC  [SHORT0402]  159.24 75.3 90 bottom
R392  330K_4  [RC0402]  158.1 75.3 90 bottom
R393  33_4  [RC0402]  157.08 75.3 270 bottom
R394  *0_4_SHORT_NC  [SHORT0402]  155.81 75.3 90 bottom
R395  1K_4  [RC0402]  154.67 75.3 270 bottom
R396  *1K_4_NC  [RC0402]  153.53 75.3 270 bottom
R397  49.9/F_4  [RC0402]  150.73 75.3 90 bottom
R398  Dis@4.7K_4  [RC0402]  184.39 73.82 270 bottom
R399  Dis@4.7K_4  [RC0402]  178.54 74.15 0 bottom
R400  Dis@4.99K/F_4  [RC0402]  190.61 73.9 90 bottom
R401  Dis@20K/F_4  [RC0402]  189.47 73.9 90 bottom
R402  49.9/F_4  [RC0402]  148.57 73.27 270 bottom
R403  *0_4_NC  [RC0402]  162.8 73.14 90 bottom
R404  10K_4  [RC0402]  161.78 73.14 90 bottom
R405  20K/F_4  [RC0402]  160.69 73.14 90 bottom
R406  330K_4  [RC0402]  159.67 73.14 90 bottom
R407  *330K_4_NC  [RC0402]  157.84 73.14 270 bottom
R408  33_4  [RC0402]  154.67 73.14 270 bottom
R409  33_4  [RC0402]  153.53 73.14 270 bottom
R410  22_4  [RC0402]  150.22 72.76 0 bottom
R411  33_4  [RC0402]  156.19 72.63 0 bottom
R412  *Dis@4.99K/F_4_NC  [RC0402]  190.61 71.74 90 bottom
R413  *Dis@4.99K/F_4_NC  [RC0402]  189.47 71.74 90 bottom
R414  *100K_4_NC  [RC0402]  303.64 69.84 0 bottom
R419  100K_4  [RC0402]  25.54 52.46 270 bottom
R420  0_4  [RC0402]  26.78 52.46 270 bottom
R421  *0_4_NC  [RC0402]  28.05 52.46 270 bottom
R422  4.7K  [RC0402]  235.57 59.17 270 bottom
R425  4.7K  [RC0402]  104 55.23 180 bottom
R427  *0_4_SHORT_NC  [SHORT0402]  93.45 60.18 180 bottom
R429  78.7K/F  [RC0402]  24.29 60.13 90 bottom
R430  22.1K/F  [RC0402]  25.31 60.11 90 bottom
R431  *10K_4_NC  [RC0402]  288.02 50.53 0 bottom
R433  *0_4_SHORT_NC  [SHORT0402]  286.11 49.77 90 bottom
R434  *Dis@0_4_SHORT_NC  [SHORT0402]  193.25 49.64 90 bottom
R435  1K_4  [RC0402]  288.27 47.61 90 bottom
R436  *15K_4_NC  [RC0402]  287.99 49.16 180 bottom
R438  *0_6_SHORT_NC  [SHORT0603]  97.14 48.12 180 bottom
R439  10K_4  [RC0402]  271.76 45.73 90 bottom
R440  *ShortPAD_NC  [SHORT3720]  138.49 71.66 180 top
R441  2.49K/F  [RC0402]  292.72 45.33 180 bottom
R442  45.3K/F_4  [RC0402]  240.9 44.56 180 bottom
R443  20K/F_4  [RC0402]  238.62 44.56 180 bottom
R444  10K_4  [RC0402]  295.75 40.13 0 top
R445  10K_4  [RC0402]  281.41 39.99 270 bottom
R446  *0_4_NC  [RC0402]  281.41 37.96 270 bottom
R447  24.3K/F_4  [RC0402]  240.9 43.29 180 bottom
R448  20K/F_4  [RC0402]  238.62 43.29 180 bottom
R449  *0_8_SHORT_NC  [SHORT0805]  298.56 42.66 0 bottom
R450  *0_4_SHORT_NC  [SHORT0402]  250.17 41.64 180 bottom
R451  *10K_4_NC  [RC0402]  190.61 42.53 90 bottom
R452  *15_4_NC  [RC0402]  205.21 42.28 270 bottom
R453  *0_6_NC  [RC0603]  284.51 41.95 180 bottom
R454  10K_4  [RC0402]  276.08 30.59 180 top
R455  *_0_8_SHORT_NC  [SHORT0805]  313.67 41.64 270 bottom
R456  *15_4_NC  [RC0402]  191.75 41.01 180 bottom
R457  15_4  [RC0402]  189.97 40.5 270 bottom
R458  *15_4_NC  [RC0402]  205.6 40.25 0 bottom
R459  *0_4_SHORT_NC  [SHORT0402]  243.44 40.12 0 bottom
R460  *15_4_NC  [RC0402]  191.75 39.99 180 bottom
R461  *0_4_SHORT_NC  [SHORT0402]  293.02 40.04 0 bottom
R462  *10K_4_NC  [RC0402]  205.6 39.23 0 bottom
R463  15_4  [RC0402]  191.75 38.98 0 bottom
R464  10K_4  [RC0402]  276.72 39.86 90 top
R465  *0_4_SHORT_NC  [SHORT0402]  241.16 38.85 0 bottom
R466  *0_4_SHORT_NC  [SHORT0402]  257.79 42.4 90 top
R467  *100K_4_NC  [RC0402]  214.23 37.88 0 bottom
R468  100K_4  [RC0402]  212.58 36.69 0 bottom
R469  *100K_4_NC  [RC0402]  237.98 35.42 270 bottom
R471  10K_4  [RC0402]  195.18 32.63 270 bottom
R472  *0_4_SHORT_NC  [SHORT0402]  244.33 31.61 0 bottom
R473  10K_4  [RC0402]  206.87 31.48 0 bottom
R475  *0_4_SHORT_NC  [SHORT0402]  244.33 30.47 0 bottom
R476  *0_4_SHORT_NC  [SHORT0402]  188.2 29.45 90 bottom
R477  *0_4_NC  [RC0402]  186.93 29.45 90 bottom
R478  *0_4_NC  [RC0402]  185.91 29.45 90 bottom
R479  100K_4  [RC0402]  282.43 26.4 270 top
R480  0_4  [RC0402]  277.35 38.34 270 bottom
R481  22_4  [RC0402]  105.42 43.22 0 top
R482  100K_4  [RC0402]  104.83 48.91 180 top
R483  *1.5K/F_4_NC  [RC0402]  58.91 44.36 180 top
R484  *0_4_SHORT_NC  [SHORT0402]  263.13 44.18 180 top
R485  0_4  [RC0402]  86.34 36.56 0 top
R486  0_4  [RC0402]  86.34 37.58 180 top
R487  0_4  [RC0402]  86.34 38.72 180 top
R488  0_4  [RC0402]  86.34 39.86 180 top
R489  0_4  [RC0402]  86.34 41.01 180 top
R491  1K_4  [RC0402]  125.66 114.59 180 top
R500  10K_4  [RC0402]  90.15 28.94 180 top
R501  *0_4_NC  [RC0402]  90.76 34.12 0 top
R502  100K_4  [RC0402]  277.35 40.5 90 bottom
R503  4.99K/F_4  [RC0402]  248.27 30.85 270 top
R504  1M_4  [RC0402]  247.12 30.85 270 top
R505  100K_4  [RC0402]  261.48 29.78 0 top
R506  100K_4  [RC0402]  261.48 31.05 0 top
R507  *4.7K_4_NC  [RC0402]  245.55 33.06 0 top
R508  *4.7K_4_NC  [RC0402]  260.08 37.45 0 top
R509  *4.7K_4_NC  [RC0402]  247.25 33.39 90 top
R510  *4.7K_4_NC  [RC0402]  245.55 32.04 0 top
R511  *4.7K_4_NC  [RC0402]  259.52 39.08 90 top
R512  *4.7K_4_NC  [RC0402]  248.27 33.39 90 top
R513  10K_4  [RC0402]  261.48 34.45 0 top
R517  *0_4_NC  [RC0402]  245.46 30.1 0 top
R518  4.7K_4  [RC0402]  248.78 28.82 90 top
R519  100K_4  [RC0402]  172.45 70.09 270 top
R524  *0_4_NC  [RC0402]  263.13 40.88 0 top
R525  0_4  [RC0402]  276.2 40.51 270 bottom
R526  10K/F_4  [RC0402]  302.87 26.42 0 bottom
R528  10K/F_4  [RC0402]  295.75 41.27 0 top
RN1  10KX4  [8P4R-0402-SMT]  169.78 98.81 90 bottom
RP1  10KX2  [4P2R-0404]  173.46 108.33 90 top
RP2  2.2KX2  [4P2R-0404]  152.89 108.19 0 top
RP3  10KX2  [4P2R-0404]  175.5 106.92 90 top
RP4  10KX2  [4P2R-0404]  173.34 105.4 90 top
RP5  10KX2  [4P2R-0404]  172.32 102.6 90 top
RP6  10KX2  [4P2R-0404]  172.32 100.95 90 top
RP7  10KX2  [4P2R-0404]  158.1 75.68 180 top
RP8  Dis@2.2KX2  [4P2R-0404]  173.72 64.25 90 top
RP9  2.2KX2  [4P2R-0404]  114.16 63.36 90 top
RP10  4.7KX2  [4P2R-0404]  229.73 35.04 0 top
RP11  2.2KX2  [4P2R-0404]  226.04 34.66 270 top
RP12  2.2KX2  [4P2R-0404]  236.96 29.07 180 top
RP13  10KX2  [4P2R-0404]  137.78 105.9 180 bottom
RP14  10KX2  [4P2R-0404]  163.81 101.22 270 bottom
RP15  10KX2  [4P2R-0404]  166.1 100.33 270 bottom
RP16  10KX2  [4P2R-0404]  163.94 99.44 270 bottom
RP17  10KX2  [4P2R-0404]  169.91 96.39 90 bottom
RP18  2.2KX2  [4P2R-0404]  312.91 90.79 0 bottom
RP19  10KX2  [4P2R-0404]  168.64 89.27 270 bottom
RP20  2.2KX2  [4P2R-0404]  174.23 89.01 180 bottom
RP21  2.2KX2  [4P2R-0404]  164.32 86.98 90 bottom
RP22  2.2KX2  [4P2R-0404]  172.07 86.22 270 bottom
RP23  2.2KX2  [4P2R-0404]  171.31 77.08 180 bottom
RT1  *10K/NTC_4_NC  [RC0402]  56.5 43.7 180 top
RTCBT1  BAT_CONN  [88266-0200-2P-L]  14.8 5.93 180 bottom
RTCD1  BAT54CW T/R  [UMT_213-3-1_3]  16.62 8.11 90 top
RTCR1  1K_4  [RC0402]  14.21 9 90 top
SJ1  *SJ0402_NC  [SHORT0402]  111.36 120.13 180 top
SJ2  *SJ0402_NC  [SHORT0402]  69.83 35.29 270 top
TP1  *PAD_NC  [TP2650]  119.11 112.64 0 top
TP2  *PAD_NC  [TP2650]  120.28 112.03 0 top
TP3  *PAD_NC  [TP2650]  128.23 105.83 180 bottom
TP4  *PAD_NC  [TP2650]  115.17 96.25 0 top
TP5  *PAD_NC  [TP2650]  113.9 95.87 0 top
TP6  *PAD_NC  [TP2650]  115.76 92.37 0 top
TP7  *PAD_NC  [TP2650]  114.89 90.16 0 top
TP8  *PAD_NC  [TP2650]  109.42 89.45 0 top
TP9  *  [TP2650]  204.58 86.07 0 top
TP10  *  [TP2050]  186.57 82.84 0 top
TP11  *  [TP2675]  189.62 81.62 0 top
TP12  *  [TP2675]  191.6 81.52 0 top
TP13  *  [TP2675]  287.08 43.55 0 top
TP15  *  [TP2050]  178.42 105.65 180 bottom
TP16  *  [TP2050]  177.05 105.5 180 bottom
TP17  *PAD_NC  [TP2650]  129.32 103.11 180 bottom
TP18  *  [TP2050]  178.44 100.11 180 bottom
TP19  *  [TP2050]  178.54 97.65 180 bottom
TP20  *PAD_NC  [TP2650]  114.33 92.31 180 bottom
TP21  *PAD_NC  [TP2650]  118.22 92.19 180 bottom
TP22  *PAD_NC  [TP2650]  115.62 92.17 180 bottom
TP23  *PAD_NC  [TP2650]  116.95 92.16 180 bottom
TP24  *PAD_NC  [TP2650]  113.52 91.3 180 bottom
TP25  *PAD_NC  [TP2650]  118.3 90.03 180 bottom
TP26  *PAD_NC  [TP2650]  112.86 89.7 180 bottom
TP27  *PAD_NC  [TP2650]  114.33 89.01 180 bottom
TP28  *PAD_NC  [TP2650]  115.76 88.94 180 bottom
TP29  *PAD_NC  [TP2650]  117.66 83.27 180 bottom
TP30  *  [TP2050]  175.62 83.09 180 bottom
TP31  *  [TP2675]  177.26 82.69 180 bottom
TP32  *  [TP2050]  178.68 81.86 180 bottom
TP33  *  [TP2675]  175.91 81.34 180 bottom
TP34  *  [TP2675]  176.94 79.64 180 bottom
TP35  *PAD_NC  [TP2650]  119.79 74.99 180 bottom
TP36  *  [TP2675]  288.22 46.06 180 bottom
TP37  *  [TP2675]  288.76 44.13 180 bottom
TP38  *PAD_NC  [TP2650]  121.01 110.98 0 top
TP40  *PAD_NC  [TP2650]  126.43 108.38 0 top
TP41  *PAD_NC  [TP2650]  123.02 108.24 0 top
TP43  *PAD_NC  [TP2650]  114.16 97.14 0 top
TP44  *PAD_NC  [TP2650]  112.89 96.76 0 top
TP45  *PAD_NC  [TP2650]  110.73 93.46 0 top
TP46  PAD  [TP2650]  201.28 93.46 0 top
TP47  *PAD_NC  [TP2650]  112.48 93.18 0 top
TP48  *PAD_NC  [TP2650]  168.95 88.22 0 top
TP49  *PAD_NC  [TP2650]  166.85 88.03 0 top
TP50  *PAD_NC  [TP2650]  169.07 86.3 0 top
TP51  *PAD_NC  [TP2650]  162.72 77.05 0 top
TP52  *PAD_NC  [TP2650]  161.5 76.67 0 top
TP53  *PAD_NC  [TP2650]  164.88 75.53 0 top
TP54  *PAD_NC  [TP2650]  161.27 75.37 0 top
TP56  *PAD_NC  [TP2650]  164.14 104.81 180 bottom
TP57  *PAD_NC  [TP2650]  164.52 103.59 180 bottom
TP58  *PAD_NC  [TP2650]  115.88 99.63 180 bottom
TP59  *PAD_NC  [TP2650]  114.78 98.91 180 bottom
TP60  *PAD_NC  [TP2650]  115.73 98.06 180 bottom
TP61  *PAD_NC  [TP2650]  116.87 97.04 180 bottom
TP62  PAD  [TP2650]  207.36 92.33 180 bottom
TP63  PAD  [TP2050]  207.98 83.5 180 bottom
TP64  *PAD_NC  [TP2650]  121.22 74.89 180 bottom
TP65  *PAD_NC  [TP2650]  124.82 74.84 180 bottom
TP67  *PAD_NC  [TP2650]  171.74 100.9 180 bottom
TP68  *PAD_NC  [TP2650]  169.12 92.24 0 top
TP69  *PAD_NC  [TP2650]  273.01 45.58 0 top
TP70  *PAD_NC  [TP2650]  273.08 43.29 0 top
U1  *Dis@MC74VHC1G08DFT2G_NC  [SSOP5-P-A-TOSHIBA-B]  177.27 94.35 180 top
U2  PS8407A  [QFN40-5X5-4-50P-0_75H]  310.12 82.66 90 top
U3  NCT7718W  [TSSOP8-4_9-65]  114.41 69.71 180 top
U4  Dis@G781-1P8  [MSOP8-4_9-65]  180.83 64.12 90 top
U5  74AUP1G07GW  [SOT353-1-2_125-65-5P]  113.14 55.23 90 top
U6  RTL8111G(S)/ RTL8111GUS  [QFN32-4X4-4-33P-0_9H]  289.8 47.87 90 top
U7  eS320AQ  [QFN40-5X5-4-41P-92HD99]  268.84 41.9 270 top
U9  RTS5227E  [QFN32-4X4-4-33P-0_9H]  57.77 38.09 0 top
U10  ALC290Q-GR  [QFN48-7X7-5-49P-ALC113-GR]  306.31 34.53 0 top
U12  APA2010  [TDFN8-3X3-65-9P-0_85H]  291.45 26.91 90 top
U13  N14P-GV2-S-A2  [BGA595-NVIDIA-N13P-GV2-S-A2]  193.4 93.9 0 bottom
U14  HSW_ULT_DDR3L/BGA  [BGA1168-INTEL-HASWELL]  140.83 90.42 0 bottom
U15  *TC7SH08FU_NC  [SSOP5-P-A-TOSHIBA-B]  174.73 73.65 180 bottom
U16  UP7534ARA8-15  [MSOP8-4_9-65]  307.58 65.9 90 bottom
U17  UP7534ARA8-15  [MSOP8-4_9-65]  20.05 61.2 180 bottom
U18  TPS2543ARTER  [QFN16-3X3-5-17P-WM9001]  25.69 56.22 180 bottom
U19  NS692417  [TRF-9_4-1_27-24P]  305.45 51.58 90 bottom
U21  *W25Q64FVSSIQ_NC  [SOIC8-7_9-1_27-2_16H]  198.61 40.88 270 bottom
U22  G5243A  [SOT23-5]  275.8 42.99 270 top
U23  IT8528  [LQFP128-16X16-4]  227.69 38.09 90 bottom
U24  W25Q64FVSSIQ  [SOIC8-7_9-1_27-2_16H]  200.77 32.63 90 bottom
U25  PS8330B  [QFN48-7X7-5-58P-PS8620]  254.74 31.86 0 top
U*  -  [unnamed#2]  20.18 3.67 0 top
U*#2  -  [unnamed#2]  13.95 106.16 0 top
U*#3  -  [unnamed#2]  324.98 106.03 0 top
U*#4  -  [unnamed#2]  3.16 102.35 180 bottom
U*#5  -  [unnamed#2]  322.18 106.16 180 bottom
U*#6  -  [unnamed#2]  308.85 24.24 180 bottom
VRAM1  Dis@VRAM _DDR3L_Micron_128MX16  [FBGA96-SAMSUNG-K4W2G1646B]  217.91 103.87 0 top
VRAM2  Dis@VRAM _DDR3L_Micron_128MX16  [FBGA96-SAMSUNG-K4W2G1646B]  217.91 79.62 180 top
VRAM3  Dis@VRAM _DDR3L_Micron_128MX16  [FBGA96-SAMSUNG-K4W2G1646B]  217.91 103.87 180 bottom
VRAM4  Dis@VRAM _DDR3L_Micron_128MX16  [FBGA96-SAMSUNG-K4W2G1646B]  217.91 79.62 0 bottom
Y1  24MHz  [XTL-3_2X2_5-2_2X1_7-4P]  141.84 107.43 180 bottom
Y2  Dis@27MHZ +-10PPM  [XTL-3_2X2_5-2_2X1_7]  190.48 77.46 0 bottom
Y3  32.768KHZ  [XTL-3_2X1_5-2_5-0_8H]  165.21 73.01 180 bottom
Y4  25MHz  [XTL-3_2X2_5-2_2X1_7-4P]  289.21 41.08 0 top

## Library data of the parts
C1 C5 C7 C10 C13 C14 C17-C25 C27-C37 C40-C53 C55-C60 C64-C67 C80 C81 C84 C87-C89 C91 C95 C96 C98-C100 C102-C104 C108 C114-C116 C120-C122 C125-C127 C130 C131 C135-C138 C140-C147 C149-C157 C159 C160 C162 C166-C168 C170 C171 C173 C174 C176-C185 C188 C190 C191 C193-C207 C209-C217 C219-C225 C231-C234 C236-C243 C246 C248 C250 C253 C256 C257 C259-C262 C264-C266 C268-C270 C276-C278 C280-C285 C287 C293-C299 C304 C306-C309 C314 C316 C318-C322 C324 C325 C327-C329 C332 C333 C335 C337 C341 C344-C346 C349-C351 C353 C354 C356 C358-C365 C369-C394 C397-C399 C401-C405 C408 C410 C413 C414 C416-C420 C422-C440 C442-C448 C450 C457 C458 C460-C462 C465 C471 C473 C474 C476 C479-C484 C486-C488 C490-C493 C495 C497-C499 C502-C507 C511-C513 C516 C517 C519 C520 C522-C525 C528-C531 C534 C535 C539-C542 EC1-EC3 EC5-EC8 EC10-EC13 EC15-EC23 EC33-EC38 PC4-PC6 PC8 PC9 PC11-PC15 PC17-PC19 PC21 PC22 PC27 PC29 PC30 PC32-PC34 PC36-PC39 PC42-PC44 PC46 PC47 PC50-PC59 PC61-PC63 PC65-PC67 PC69 PC70 PC74 PC79-PC83 PC88-PC95 PC98 PC102-PC109 PC111 PC113 PC114 PC118 PC119 PC125-PC128 PC136 PC137 PC139 PC143 PC150 PC153 PC157 PC158 PC160-PC162 PC166 PC167 PC171 PC174 PC176-PC182 PC186-PC188 PC193-PC196 PC198-PC200 PC241 PC249 PC250 PC252 PC254 = CC0402
C2-C4 C6 C8 C9 C11 C12 C15 C16 C26 C38 C39 C54 C61-C63 C68-C79 C82 C83 C85 C86 C90 C92-C94 C97 C101 C105-C107 C109-C113 C117-C119 C123 C124 C128 C129 C132-C134 C139 C148 C158 C161 C163-C165 C169 C172 C175 C186 C187 C189 C192 C208 C218 C226-C230 C244 C245 C249 C251 C252 C254 C255 C258 C263 C272-C274 C279 C289 C292 C300-C303 C305 C315 C317 C323 C326 C330 C338 C342 C343 C352 C355 C395 C406 C407 C409 C411 C412 C415 C421 C451-C456 C459 C464 C472 C477 C478 C494 C496 C500 C501 C508-C510 C514 C515 C518 C521 C532 C536 EC4 EC9 EC14 EC24 PC10 PC16 PC20 PC26 PC28 PC31 PC35 PC40 PC41 PC48 PC60 PC64 PC72 PC73 PC75-PC78 PC84-PC87 PC110 PC115-PC117 PC120-PC124 PC129-PC135 PC140 PC144 PC240 PC251 PC253 = CC0603
C441 C463 C466-C468 C470 C475 C537 C538 PC1-PC3 PC7 PC68 PC71 PC96 PC97 PC101 PC112 PC138 PC152 PC154 PC155 PC159 PC164 PC165 PC169 PC170 PC183-PC185 PC189-PC192 PC197 = CC0805
C449 = CC3528
C469 = CC1808
CN1 = GS12203-1011-9F-20P-R
CN2 = DCJK-2DC3074-000111F-2P
CN3 = HDMI-2HE1608-000111F-19P-LDV
CN4 CN5 = USB-YBA-USB-032-P01-9P-RUH-SMT
CN6 = USB-YUSB0012-P001A-10P
CN7 = RJ45-JM361C-HP34AA03-9H-8P
CN8 = 88513-0601-6P-L-SMT
CN9 = SDCARD-CS1M-098-H-N-11P
CN10 = 50281-0060N-001-6P-L-SMT
CN11 = GS12301-1011A-9F-30P-L-SMT
CN12 = PHJK-2SJ3061-021111F-7P
CN14 = MIPCI-APCI0019-P002A-75P-KE
CN15 = 50503-0080N-001-8P-L
CN16 = BL135H-32RLA-TAND-32P-L-SMT
CN17 = SATA-C166G1-12208-L-22P-R
CN18 = 50456-00841-001-8P-L
D1 D5 D8-D12 D15 D19-D21 PD2 PD5 PD8 = DSMV
D2 D3 PD3 PD4 PD6 PD7 = DSM
